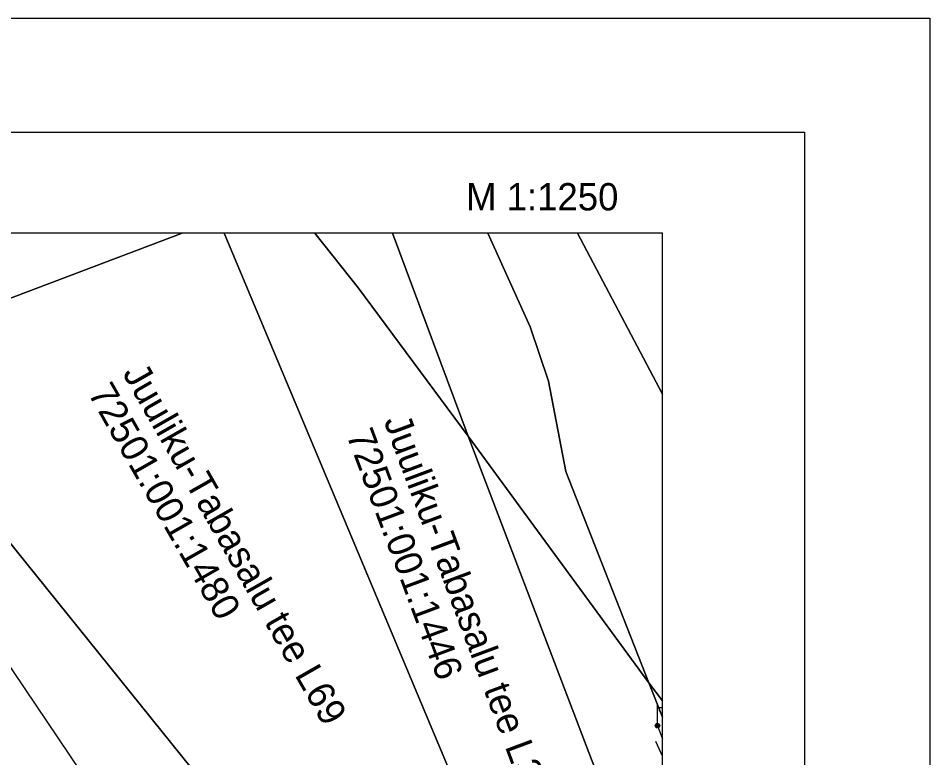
# Model space of a CAD drawing. Extents: x 532656 to 533339, y 6581345 to 6581629.
# Drawn here: x 533238.9 to 533338.9, y 6581547.8 to 6581629 of the extents above; entities that cross this region are included whole.
import ezdxf

# ---------------------------------------------------------------- set-up
doc = ezdxf.new("R2010")
doc.units = 0
for name, color, linetype in [('KPOHULIIN', 7, 'Continuous'), ('MPKAABEL', 7, 'Continuous'), ('PIIR', 7, 'Continuous'), ('POST', 7, 'Continuous'), ('TEE', 7, 'Continuous'), ('VORMISTUS', 7, 'Continuous')]:
    doc.layers.add(name, color=color, linetype=linetype)

msp = doc.modelspace()

# ---------------------------------------------------------------- linework, layer by layer
at = {"layer": 'KPOHULIIN'}
msp.add_lwpolyline([(533284.7, 6581494.9), (533275.32, 6581502.37), (533233.4, 6581564.58)], dxfattribs=at)
at = {"layer": 'MPKAABEL'}
msp.add_lwpolyline([(533308.96, 6581551.4), (533309.05, 6581551.33), (533309.59, 6581549.9)], dxfattribs=at)
at = {"layer": 'PIIR'}
for p, q in [((533309.59, 6581587.73), (533300.26, 6581605.42)), ((533300.26, 6581605.42), (533309.59, 6581587.73))]:
    msp.add_line(p, q, dxfattribs=at)
for points in [[(533256.87, 6581605.42), (533221.38, 6581591.97), (533210.54, 6581605.42)], [(533261.48, 6581605.42), (533291.41, 6581534.01), (533271.76, 6581529.44), (533221.38, 6581591.97), (533256.87, 6581605.42)], [(533309.59, 6581500.16), (533303.4, 6581511.09), (533294.3, 6581527.13), (533291.41, 6581534.01), (533261.48, 6581605.42)], [(533279.97, 6581605.42), (533288.27, 6581583.12), (533276.24, 6581599.38), (533271.42, 6581605.42)], [(533271.42, 6581605.42), (533276.24, 6581599.38), (533288.27, 6581583.12), (533301.8, 6581547.63), (533309.59, 6581528.4)], [(533290.43, 6581605.42), (533295.08, 6581595.11), (533297.1, 6581589.15), (533299.01, 6581579.24), (533308.1, 6581556.05), (533288.27, 6581583.12), (533279.97, 6581605.42)], [(533309.59, 6581554.07), (533308.1, 6581556.05), (533299.01, 6581579.24), (533297.1, 6581589.15), (533295.08, 6581595.11), (533290.43, 6581605.42)], [(533309.59, 6581528.4), (533301.8, 6581547.63), (533288.27, 6581583.12), (533308.1, 6581556.05), (533309.59, 6581552.26)], [(533309.59, 6581552.26), (533308.1, 6581556.05), (533309.59, 6581554.07)]]:
    msp.add_lwpolyline(points, dxfattribs=at)
msp.add_lwpolyline([(533221.38, 6581591.97), (533271.76, 6581529.44), (533205.25, 6581513.98), (533173.8, 6581529.09), (533143.65, 6581562.67), (533194.1, 6581581.68)], close=True, dxfattribs=at)
at = {"layer": 'POST'}
for p, q in [((533309.05, 6581551.58), (533309.05, 6581553.58)), ((533309.05, 6581553.33), (533309.59, 6581553.33)), ((533309.28, 6581553.01), (533309.28, 6581553.33)), ((533309.05, 6581551.33), (533309.05, 6581551.33))]:
    msp.add_line(p, q, dxfattribs=at)
for radius in [0.25, 0.225, 0.2, 0.175, 0.15, 0.125, 0.1, 0.075, 0.05, 0.025]:
    msp.add_circle((533309.05, 6581551.33), radius, dxfattribs=at)
msp.add_arc((533309.59, 6581553.01), 0.306, 180, 271.739, dxfattribs=at)
at = {"layer": 'TEE'}
msp.add_line((533309.59, 6581547.98), (533308.89, 6581549.6), dxfattribs=at)
at = {"layer": 'VORMISTUS'}
for points in [[(532967.7, 6581629.01), (533338.95, 6581629.01), (533338.95, 6581366.51), (532967.7, 6581366.51)], [(532981.45, 6581379.01), (532981.45, 6581616.51), (533325.2, 6581616.51), (533325.2, 6581379.01)], [(532981.45, 6581616.51), (533325.2, 6581616.51), (533325.2, 6581379.01), (532981.45, 6581379.01)], [(533309.59, 6581421.68), (533309.59, 6581605.42), (532997.7, 6581605.42), (532997.7, 6581421.68)]]:
    msp.add_lwpolyline(points, close=True, dxfattribs=at)
for points in [[(533309.59, 6581605.42), (532997.7, 6581605.42)], [(533309.59, 6581421.68), (533309.59, 6581605.42)]]:
    msp.add_lwpolyline(points, dxfattribs=at)

# ---------------------------------------------------------------- texts
at = {"layer": 'PIIR'}
for s, rotation, p in [('Juuliku-Tabasalu tee L69', 299.7216, (533250.26, 6581590.03)), ('72501:001:1480', 299.7216, (533246.46, 6581587.86)), ('Juuliku-Tabasalu tee L37', 290.413, (533278.97, 6581584.81)), ('72501:001:1446', 290.413, (533274.87, 6581583.28))]:
    msp.add_text(s, height=3, rotation=rotation, dxfattribs=at).set_placement(p)
at = {"layer": 'VORMISTUS'}
msp.add_text('M 1:1250', height=3, rotation=360, dxfattribs=at).set_placement((533288.04, 6581607.91))

doc.saveas('drawing.dxf')
